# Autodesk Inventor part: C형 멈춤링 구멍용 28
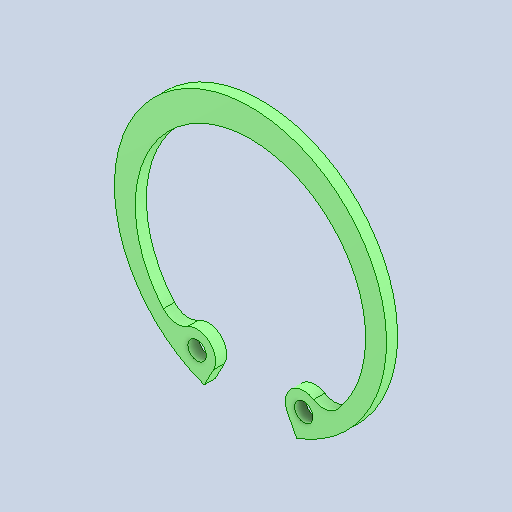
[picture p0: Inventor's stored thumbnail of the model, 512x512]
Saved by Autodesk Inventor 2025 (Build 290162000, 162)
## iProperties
Created: 2026-07
Part Number: C형 멈춤링 구멍용 28
Material: 강철, 연강
Description: 리테이닝 링(C형)
Document SubType Name: Modeling
Designer: KDI
Density: 7.85 g/cm^3
Appearance: 기본값
Author: jhkim
Sending System: Autodesk Inventor 2027
Preprocessor: ST-DEVELOPER v20.1
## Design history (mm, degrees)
feature "Solid1"
node "솔리드1"
